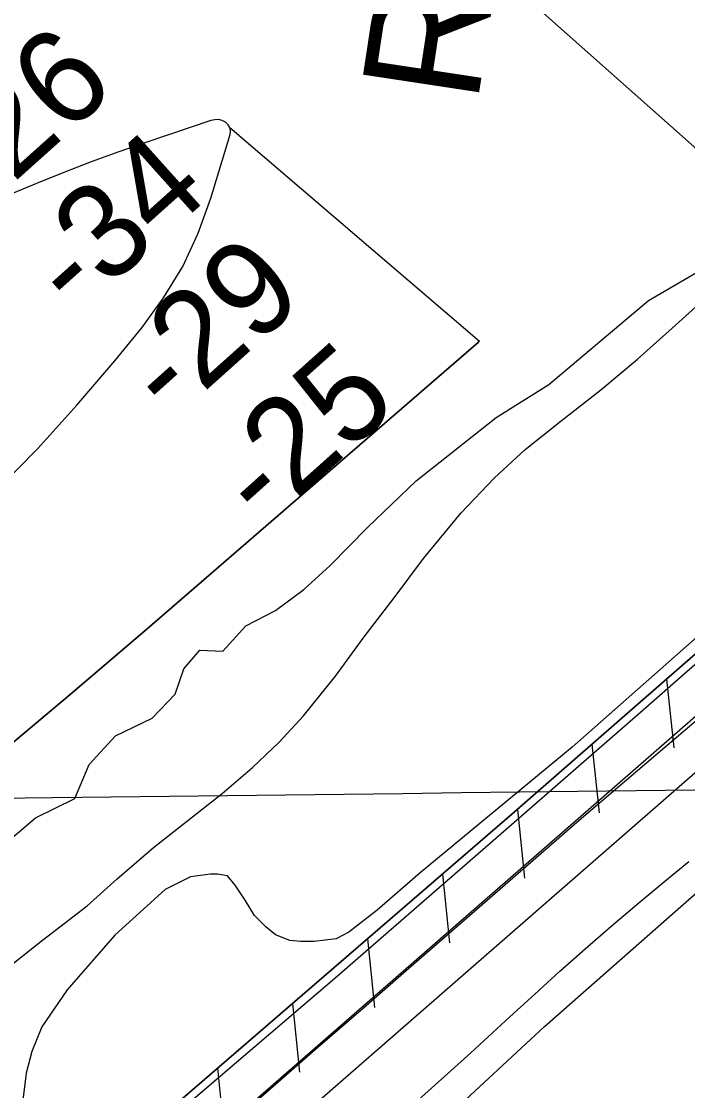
# Model space of a CAD drawing. Extents: x 3704301 to 3742427, y 506229 to 532009.
# Drawn here: x 3713220 to 3713691, y 517556 to 518312 of the extents above; entities that cross this region are included whole.
import ezdxf

# ---------------------------------------------------------------- set-up
doc = ezdxf.new("R2010")
doc.units = 0
for name, color, linetype in [('V-FLOD-BASE', 7, 'Continuous'), ('V-GRID-MAJR', 7, 'Continuous'), ('V-LEVE-TOET', 7, 'Continuous'), ('V-RIVR-EDGE', 7, 'Continuous'), ('V-RIVR-RANG', 7, 'Continuous'), ('V-RIVR-RANG-IDEN', 7, 'Continuous'), ('V-RRAP-FSHR', 7, 'Continuous'), ('V-SITE-VEGE', 7, 'Continuous'), ('V-SURV-LINE', 7, 'Continuous'), ('V-TOPO-DPTH', 7, 'Continuous'), ('V-TOPO-MINR', 7, 'Continuous'), ('V-UTIL-LINE', 7, 'Continuous')]:
    doc.layers.add(name, color=color, linetype=linetype)

msp = doc.modelspace()

# ---------------------------------------------------------------- linework, layer by layer
at = {"layer": 'V-FLOD-BASE'}
msp.add_lwpolyline([(3713365.5, 517530.25), (3713397.48, 517558.32), (3713429.5, 517586.34), (3713461.58, 517614.31), (3713493.71, 517642.22), (3713525.88, 517670.08), (3713614.09, 517746.86), (3713709.85, 517828.39)], dxfattribs=at)
at = {"layer": 'V-GRID-MAJR'}
for points in [[(3713850.36, 511710.7), (3713778.1, 517769.29), (3713705.82, 523829.82), (3713633.53, 529890.36), (3713633.51, 529892.28)], [(3708498.53, 517706.7), (3713778.1, 517769.29), (3719057.66, 517832.65), (3724337.21, 517896.77), (3729616.75, 517961.66), (3734896.28, 518027.32), (3740175.8, 518093.74), (3740175.81, 518093.74)]]:
    msp.add_spline(points, degree=3, dxfattribs=at)
at = {"layer": 'V-LEVE-TOET'}
for points in [[(3713767.3, 517919.29), (3713657.39, 517823.07), (3713546.07, 517725.9), (3713441.35, 517634.9), (3713315.4, 517527.29)], [(3713426.19, 517482.65), (3713454.18, 517507.44), (3713482.06, 517532.35), (3713509.84, 517557.37), (3713537.51, 517582.5), (3713565.08, 517607.75), (3713582.71, 517623.98), (3713600.5, 517640.05), (3713618.44, 517655.94), (3713636.54, 517671.66), (3713654.78, 517687.21), (3713673.18, 517702.57), (3713691.72, 517717.76)]]:
    msp.add_lwpolyline(points, dxfattribs=at)
at = {"layer": 'V-RIVR-EDGE'}
msp.add_lwpolyline([(3713002.44, 517524.48), (3713089.05, 517591.5), (3713164.26, 517659.15), (3713197.43, 517720.9), (3713229.92, 517748.44), (3713257.57, 517762.18), (3713267.83, 517786.16), (3713286.49, 517806.53), (3713312.34, 517819.07), (3713328.59, 517835.84), (3713334.64, 517853.84), (3713346.08, 517867.01), (3713362.28, 517866.37), (3713378.54, 517884.34), (3713399.57, 517895.1), (3713419.42, 517910.06), (3713438.07, 517926.82), (3713464.55, 517953.77), (3713498.85, 517986.7), (3713555.4, 518031.59), (3713592.67, 518054.91), (3713663.06, 518114.17), (3713740.61, 518159.6)], dxfattribs=at)
at = {"layer": 'V-RRAP-FSHR'}
for p, q in [((3713675.86, 517846.59), (3713681.08, 517798.04)), ((3713623.14, 517800.55), (3713628.36, 517751.99)), ((3713570.44, 517754.47), (3713575.37, 517705.89)), ((3713517.45, 517708.74), (3713522.37, 517660.16)), ((3713464.45, 517663.01), (3713469.38, 517614.43)), ((3713411.46, 517617.27), (3713416.38, 517568.69)), ((3713358.46, 517571.54), (3713363.39, 517522.96))]:
    msp.add_line(p, q, dxfattribs=at)
for points in [[(3712747.27, 517178.52), (3712769.92, 517185.99), (3712814.21, 517196.07), (3712943.47, 517232.17), (3712973.34, 517249.67), (3712995.21, 517262.63), (3713013.97, 517275.48), (3713027.07, 517283.92), (3713276.94, 517501.19), (3713566.47, 517751.05), (3713802.05, 517956.81)], [(3713802.05, 517956.81), (3713566.47, 517751.05), (3713276.94, 517501.19), (3713027.07, 517283.92), (3713013.97, 517275.48), (3712995.21, 517262.63), (3712973.34, 517249.67), (3712943.47, 517232.17), (3712814.21, 517196.07), (3712769.92, 517185.99), (3712747.27, 517178.52)]]:
    msp.add_lwpolyline(points, dxfattribs=at)
at = {"layer": 'V-SITE-VEGE'}
for points in [[(3713199.21, 517633.91), (3713234.82, 517661.95), (3713266.28, 517686.4), (3713287.64, 517705.48), (3713313.16, 517727.54), (3713337.5, 517746.63), (3713361.83, 517765.72), (3713383.19, 517784.2), (3713402.18, 517802.09), (3713419.38, 517820.56), (3713441.91, 517848.57), (3713462.06, 517876.57), (3713483.4, 517903.97), (3713504.15, 517931.97), (3713530.83, 517964.14), (3713553.96, 517988.58), (3713575.92, 518008.85), (3713601.44, 518029.13), (3713629.34, 518051.2), (3713655.45, 518072.67), (3713679.78, 518094.73), (3713708.26, 518120.36)], [(3713697.55, 517876.53), (3713609.13, 517798.42), (3713501.71, 517709.56), (3713471.44, 517683.32)], [(3713471.44, 517683.32), (3713451.26, 517667.81), (3713442.35, 517663.04), (3713426.9, 517661.22), (3713417.38, 517661.19), (3713409.65, 517661.77), (3713399.53, 517665.91), (3713392.98, 517671.24), (3713384.63, 517679.55), (3713378.07, 517690.24), (3713370.9, 517700.92), (3713365.54, 517707.45), (3713358.4, 517708.62), (3713353.64, 517708.61), (3713339.37, 517706.79), (3713321.56, 517697.83), (3713285.95, 517665.64), (3713252.15, 517626.9), (3713234.37, 517600.69), (3713227.28, 517583.43), (3713223.15, 517567.96), (3713220.82, 517548.93)], [(3712928.81, 517074.09), (3713035.4, 517123.13), (3713136.08, 517186.47), (3713172.92, 517219.43), (3713231.62, 517271.48), (3713326, 517359.37), (3713451.47, 517472.72), (3713589.58, 517601.09), (3713705.27, 517702.87)]]:
    msp.add_lwpolyline(points, dxfattribs=at)
at = {"layer": 'V-SURV-LINE'}
for points in [[(3713051.76, 517258.38), (3714482.39, 518506.02)], [(3714502.12, 518483.42), (3713071.49, 517235.78)]]:
    msp.add_lwpolyline(points, dxfattribs=at)
at = {"layer": 'V-TOPO-DPTH'}
msp.add_line((3713367.23, 518236.47), (3713367.23, 518236.47), dxfattribs=at)
for points in [[(3713202.38, 517980.08), (3713231.39, 518009.54), (3713259.12, 518040.21), (3713285.99, 518071.68), (3713304.96, 518094.87), (3713320.32, 518116.09), (3713333.87, 518138.28), (3713344.71, 518161.9), (3713353.76, 518186.48), (3713367.37, 518231.59), (3713367.59, 518234.14), (3713367.23, 518236.47), (3713365.99, 518238.48), (3713364.18, 518240.28), (3713361.69, 518241.43), (3713359.14, 518242.11), (3713356.51, 518242.07), (3713353.82, 518241.56), (3713308.47, 518226.23), (3713288.83, 518219.37), (3713269.29, 518212.26), (3713249.89, 518204.76), (3713230.58, 518197.01), (3713204.13, 518186.09)], [(3713367.23, 518236.47), (3713543.63, 518085.45), (3713542.9, 518084.78), (3713308.78, 517882.16), (3713254.34, 517835.69), (3713199.47, 517789.74), (3713143.98, 517744.55), (3713088.06, 517699.87), (3712975.59, 517611.27), (3712901.02, 517701.61)], [(3712901.02, 517701.61), (3713172.53, 517951.42), (3713202.38, 517980.08), (3713231.39, 518009.54), (3713259.12, 518040.21), (3713285.99, 518071.68), (3713304.96, 518094.87), (3713320.32, 518116.09), (3713333.87, 518138.28), (3713344.71, 518161.9), (3713353.76, 518186.48), (3713367.37, 518231.59), (3713367.59, 518234.14), (3713367.23, 518236.47)]]:
    msp.add_lwpolyline(points, dxfattribs=at)
at = {"layer": 'V-TOPO-MINR'}
for points in [[(3713202.38, 517980.08), (3713231.39, 518009.54), (3713259.12, 518040.21), (3713285.99, 518071.68), (3713304.96, 518094.87), (3713320.32, 518116.09), (3713333.87, 518138.28), (3713344.71, 518161.9), (3713353.76, 518186.48), (3713367.37, 518231.59), (3713367.59, 518234.14), (3713367.23, 518236.47), (3713365.99, 518238.48), (3713364.18, 518240.28), (3713361.69, 518241.43), (3713359.14, 518242.11), (3713356.51, 518242.07), (3713353.82, 518241.56), (3713308.47, 518226.23), (3713288.83, 518219.37), (3713269.29, 518212.26), (3713249.89, 518204.76), (3713230.58, 518197.01), (3713204.13, 518186.09)], [(3712975.59, 517611.27), (3713088.06, 517699.87), (3713143.98, 517744.55), (3713199.47, 517789.74), (3713254.34, 517835.69), (3713308.78, 517882.16), (3713542.9, 518084.78), (3713543.63, 518085.45)]]:
    msp.add_lwpolyline(points, dxfattribs=at)
at = {"layer": 'V-UTIL-LINE'}
msp.add_line((3713322.59, 518554.43), (3713818.36, 518113.41), dxfattribs=at)

# ---------------------------------------------------------------- texts
at = {"layer": 'V-RIVR-RANG'}
for s, p in [('-26', (3713191.64, 518176.92)), ('-26', (3713191.64, 518176.92)), ('-34', (3713258.37, 518102.44)), ('-34', (3713258.37, 518102.44)), ('-29', (3713325.69, 518028.5)), ('-29', (3713325.69, 518028.5)), ('-25', (3713391.24, 517952.96)), ('-25', (3713391.24, 517952.96))]:
    msp.add_text(s, height=67, rotation=41.86833, dxfattribs=at).set_placement(p)
at = {"layer": 'V-RIVR-RANG-IDEN'}
msp.add_text('R-88.3', height=83, rotation=81.37631, dxfattribs=at).set_placement((3713542.08, 518252.44))

doc.saveas('drawing.dxf')
